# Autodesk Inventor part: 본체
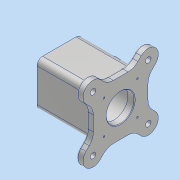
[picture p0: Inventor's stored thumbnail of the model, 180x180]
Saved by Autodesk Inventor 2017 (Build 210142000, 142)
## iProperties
Part Number: 본체
Material: 알루미늄 6061
Document SubType Name: Modeling
Designer: MRC
Mass: 1076.28 g
Surface Area: 879.964 cm^2
Volume: 398.62 cm^3
Density: 2.7 g/cm^3
Appearance: 알루미늄 - 평지
Author: MRC
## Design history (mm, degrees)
sketch "스케치1"
  geometry: L1 (-49, 40)-(61, 40); L2 (61, 40)-(61, -40); L3 (61, -40)-(-49, -40); L4 (-49, -40)-(-49, 40); 2 further points
  constraints: 8 end point, 2 parallel, 1 horizontal, 1 horizontal alignment, 1 midpoint, 1 perpendicular
  dimensions: "d0" = 110 distance of L1.start L1.end; "d1" = 61 distance from line of point (0, 0) L2; "d2" = 80 distance of L3.end L1.start
extrude "돌출1" new body sketch "스케치1" stored distance "d3" = 80; taper "d4" = 0 deg
fillet "모깎기1" dims "d5" = 10
sketch "스케치2"
  geometry: C1 r 25 at (40, 30); 1 further point
  constraints: 1 centre point, 1 coincident
  dimensions: "d6" = 50 diameter of C1
extrude "돌출2" cut sketch "스케치2" distance "d7" = 12; taper "d8" = 0 deg
sketch "스케치3"
  geometry: C1 r 25 at (40, 30); 1 further point
  constraints: 1 centre point, 1 coincident
  dimensions: "d9" = 50 diameter of C1
extrude "돌출3" cut sketch "스케치3" distance "d10" = 12; taper "d11" = 0 deg
sketch "스케치4"
  geometry: C1 r 25 at (0, 0) reference; C2 r 35 at (0, 0)
  constraints: 1 centre point, 1 coincident
  dimensions: "d12" = 70 diameter of C2
extrude "돌출4" cut sketch "스케치4" distance "d13" = 86; taper "d14" = 0 deg
sketch "스케치5"
  geometry: L1 (10, 0)-(70, 0); L2 (70, 0)-(70, 60); L3 (70, 60)-(10, 60); L4 (10, 60)-(10, 0); L5 (10, 0)-(70, 60); L6 (70, 0)-(10, 60); C1 r 25 at (40, 30) reference; A1 r 10 centre (70, 60) between (80, 60) and (70, 70) reference; 4 further points
  constraints: 12 end point, 4 coincident, 2 midpoint, 2 parallel, 1 horizontal, 1 perpendicular
  dimensions: "d15" = 60 distance of L2.end L1.end (derived)
hole "구멍1" sketch "스케치5" at (10, 60), (70, 60), (70, 0), (10, 0) diameter "d16" = 3.242; stored, may be unused: countersink angle "d20" = 90 deg, drill point angle "d22" = 118 deg; dims "d17" = 8, "d18" = 4, "d19" = 2, "d21" = 10
node "작업 평면1"
sketch "스케치6"
  geometry: L1 (-9.497, 79.497)-(89.497, -19.497); L2 (89.497, 79.497)-(-9.497, -19.497); L3 (40, 30)-(40, 100); L4 (-9, -19)-(89, -19); L5 (89, -19)-(89, 79); L6 (89, 79)-(-9, 79); L7 (-9, 79)-(-9, -19); L8 (-9, -19)-(89, 79); L9 (89, -19)-(-9, 79); L10 (76.77, 92.225)-(63.544, 79); L11 (102.225, 66.77)-(89, 53.544); C1 r 1.621 at (10, 0) reference; C2 r 1.621 at (70, 60) reference; C3 r 1.621 at (10, 60) reference; C4 r 1.621 at (70, 0) reference; C5 r 25 at (40, 30) reference; C6 r 18 at (-9.497, 79.497); C7 r 18 at (89.497, -19.497); C8 r 18 at (-9.497, -19.497); A1 r 70 centre (40, 30) between (-9.497, 79.497) and (89.497, 79.497); A2 r 18 centre (89.497, 79.497) between (76.77, 92.225) and (102.225, 66.77); 1 further point
  constraints: 22 end point, 7 point on circle, 5 centre point, 4 midpoint, 4 parallel, 3 coincident, 2 point on line, 2 tangent, 1 horizontal, 1 perpendicular, 1 vertical
  dimensions: "d23" = 140 diameter of A1; "d24" = 36 diameter of C6; "d25" = 36 diameter of A2; "d26" = 36 diameter of C7; "d27" = 36 diameter of C8; "d29" = 45 deg angle of L3 L2; "d30" = 45 deg angle of L3 L1; "d31" = 98 distance of L6.end L5.end; "d32" = 98 distance of L5.end L4.end
extrude "돌출5" join sketch "스케치6" distance "d49" = 12; taper "d50" = 0 deg
fillet "모깎기5" dims "d82" = 25
sketch "스케치7"
  geometry: C1 r 20 at (49, 30); 1 further point
  constraints: 1 centre point, 1 coincident
  dimensions: "d51" = 40 diameter of C1
extrude "돌출6" join sketch "스케치7" distance "d52" = 15; taper "d53" = 0 deg
hole "구멍2" diameter "d56" = 25; stored, may be unused: countersink angle "d60" = 90 deg, drill point angle "d62" = 0 deg; dims "d54" = 10, "d55" = 10, "d57" = 8, "d58" = 30, "d59" = 8, "d61" = 10
chamfer "모따기1" distance "d63" = 1; stored, may be unused: second distance "d64" = 2, angle "d65" = 45 deg
fillet "모깎기2" dims "d66" = 3
sketch "스케치8"
  geometry: A1 r 15 centre (-89.497, 79.497) between (-78.891, 90.104) and (-100.104, 68.891) reference; A2 r 15 centre (-89.497, -19.497) between (-100.104, -8.891) and (-78.891, -30.104) reference; A3 r 15 centre (9.497, -19.497) between (-1.109, -30.104) and (20.104, -8.891) reference; A4 r 15 centre (9.497, 79.497) between (20.104, 68.891) and (-1.109, 90.104) reference; 13 further points
  constraints: 4 coincident
hole "구멍3" sketch "스케치8" at (-89.497, 79.497), (-89.497, -19.497), (9.497, -19.497), (9.497, 79.497) diameter "d67" = 10; stored, may be unused: countersink angle "d71" = 90 deg, drill point angle "d73" = 0 deg; dims "d68" = 8, "d69" = 18, "d70" = 4, "d72" = 10
fillet "모깎기3" dims "d74" = 3
sketch "스케치9"
  geometry: L1 (0, 60)-(0, 0) reference; C1 r 20 at (49, 30) reference; 1 further point
  constraints: 1 horizontal alignment, 1 other
  dimensions: "d75" = 10 distance from line of L1 point (10, 30)
feature "엠보싱1" sketch "스케치9" dims "d0" = 110, "d1" = 61, "d2" = 80, "d76" = 0.5, "d77" = 0
fillet "모깎기4" dims "d78" = 3
node "솔리드1"
mirror "미러1"
pattern_circular "원형 패턴1" dims angle "d80" = 360 deg
pattern_circular "원형 패턴2" dims angle "d84" = 360 deg
